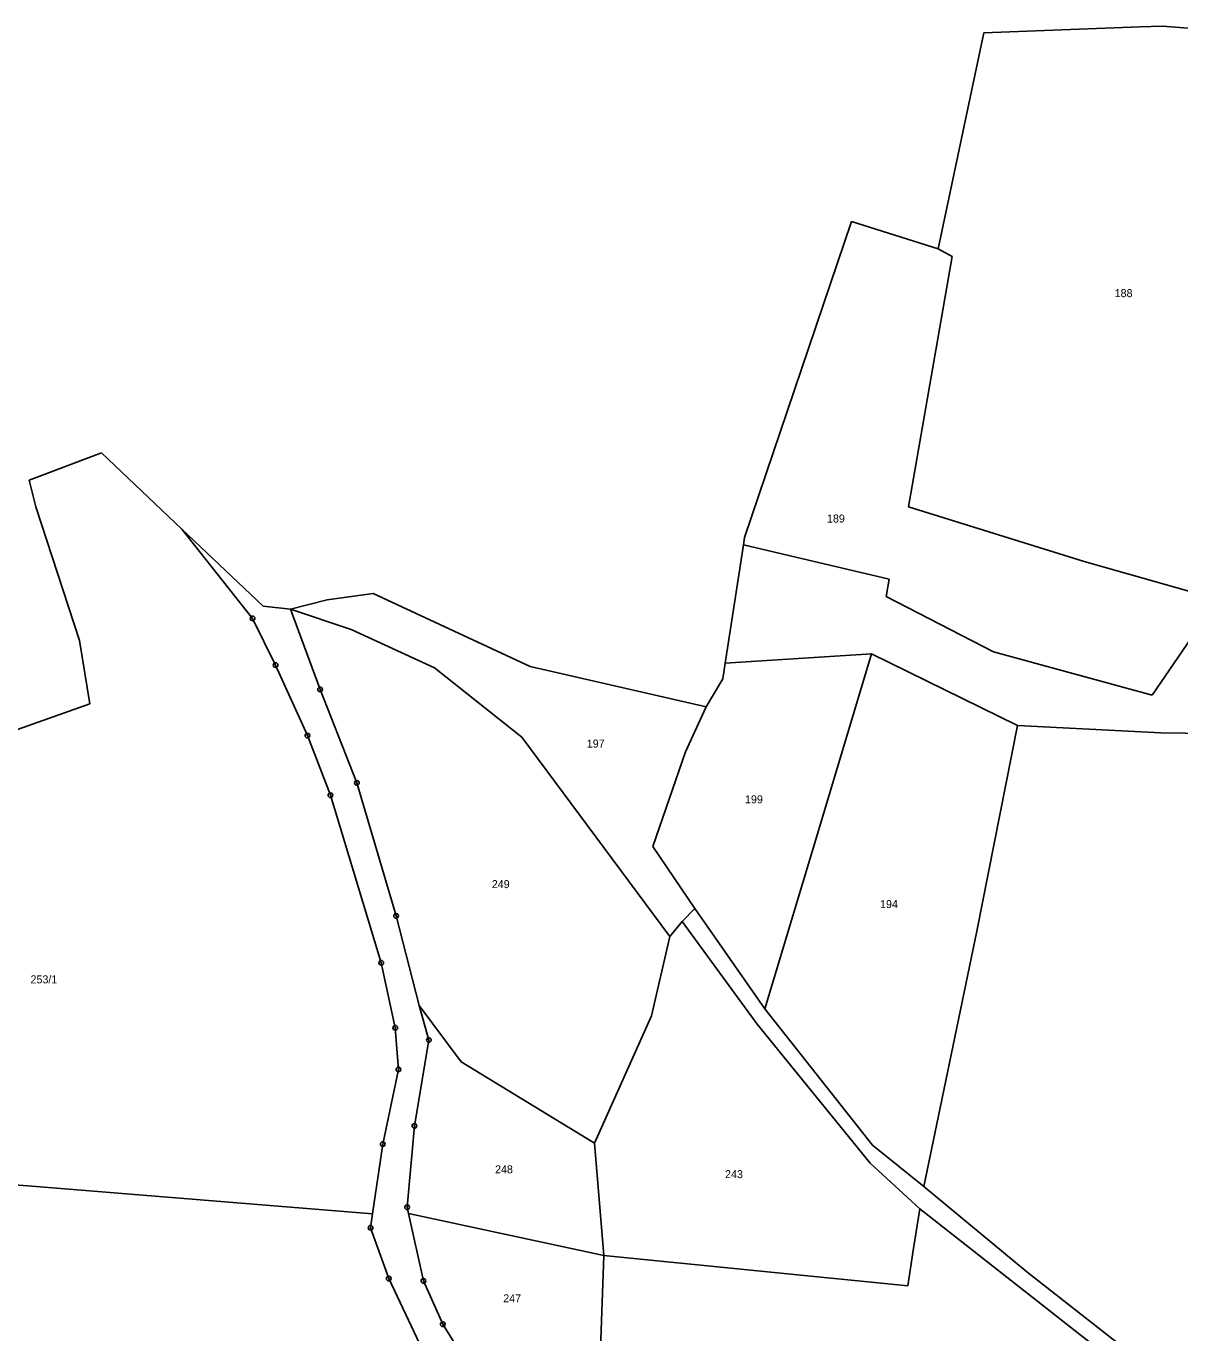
# Model space of a CAD drawing. Extents: x -791548 to -789311, y -1142631 to -1140855.
# Drawn here: x -790850.9 to -790605.8, y -1141528.8 to -1141251.3 of the extents above; entities that cross this region are included whole.
import ezdxf
from ezdxf.enums import TextEntityAlignment as Align

# ---------------------------------------------------------------- set-up
doc = ezdxf.new("R2010")
doc.units = 0
doc.header["$LTSCALE"] = 0.68
doc.layers.add('1', color=7, linetype='Continuous', lineweight=25)
doc.layers.add('8', color=7, linetype='Continuous', lineweight=25)
doc.layers.add('2', color=7, linetype='Continuous')

msp = doc.modelspace()

# ---------------------------------------------------------------- linework, layer by layer
at = {"layer": '1'}
for p, q in [((-790614.36, -1141251.45), (-790647.44, -1141252.67)), ((-790609.55, -1141251.27), (-790614.36, -1141251.45)), ((-790574.52, -1141254.07), (-790609.55, -1141251.27)), ((-790647.44, -1141252.67), (-790657.14, -1141298.57)), ((-790675.61, -1141292.79), (-790698.28, -1141359.89)), ((-790657.14, -1141298.57), (-790675.61, -1141292.79)), ((-790654.21, -1141300.21), (-790657.14, -1141298.57)), ((-790663.5, -1141353.35), (-790654.21, -1141300.21)), ((-790834.89, -1141341.93), (-790850.23, -1141347.68)), ((-790817.82, -1141358.13), (-790834.89, -1141341.93)), ((-790850.23, -1141347.68), (-790848.82, -1141353.4)), ((-790848.82, -1141353.4), (-790839.58, -1141381.74)), ((-790626.13, -1141364.99), (-790663.5, -1141353.35)), ((-790800.56, -1141374.5), (-790817.82, -1141358.13)), ((-790817.82, -1141358.13), (-790802.79, -1141377.08)), ((-790702.42, -1141386.57), (-790698.52, -1141361.44)), ((-790698.52, -1141361.44), (-790698.28, -1141359.89)), ((-790698.52, -1141361.44), (-790667.55, -1141368.7)), ((-790601.94, -1141371.83), (-790626.13, -1141364.99)), ((-790667.55, -1141368.7), (-790668.23, -1141372.38)), ((-790786.92, -1141373.1), (-790794.77, -1141375.11)), ((-790777.15, -1141371.81), (-790786.92, -1141373.1)), ((-790743.82, -1141387.29), (-790777.15, -1141371.81)), ((-790668.23, -1141372.38), (-790645.38, -1141384.2)), ((-790794.77, -1141375.11), (-790800.56, -1141374.5)), ((-790788.45, -1141392.15), (-790794.77, -1141375.11)), ((-790794.77, -1141375.11), (-790781.85, -1141379.43)), ((-790802.79, -1141377.08), (-790797.92, -1141386.98)), ((-790839.58, -1141381.74), (-790837.35, -1141395.22)), ((-790781.85, -1141379.43), (-790764.16, -1141387.55)), ((-790611.73, -1141393.4), (-790603.44, -1141381.28)), ((-790702.42, -1141386.57), (-790671.34, -1141384.61)), ((-790681.9, -1141419.8), (-790671.34, -1141384.61)), ((-790671.34, -1141384.61), (-790640.29, -1141399.79)), ((-790645.38, -1141384.2), (-790611.73, -1141393.4)), ((-790797.92, -1141386.98), (-790791.15, -1141401.95)), ((-790706.45, -1141395.88), (-790743.82, -1141387.29)), ((-790702.94, -1141389.91), (-790702.42, -1141386.57)), ((-790764.16, -1141387.55), (-790745.6, -1141402.32)), ((-790702.94, -1141389.91), (-790706.45, -1141395.88)), ((-790780.64, -1141412), (-790788.45, -1141392.15)), ((-790837.35, -1141395.22), (-790890.23, -1141413.86)), ((-790710.85, -1141405.42), (-790706.45, -1141395.88)), ((-790648.97, -1141443.49), (-790640.29, -1141399.79)), ((-790640.29, -1141399.79), (-790609.89, -1141401.37)), ((-790609.89, -1141401.37), (-790575.13, -1141401.94)), ((-790791.15, -1141401.95), (-790786.26, -1141414.61)), ((-790745.6, -1141402.32), (-790714.19, -1141444.6)), ((-790717.81, -1141425.51), (-790710.85, -1141405.42)), ((-790772.31, -1141440.24), (-790780.64, -1141412)), ((-790786.26, -1141414.61), (-790775.45, -1141450.21)), ((-790693.99, -1141460.01), (-790681.9, -1141419.8)), ((-790708.84, -1141438.68), (-790717.81, -1141425.51)), ((-790767.42, -1141459.28), (-790772.31, -1141440.24)), ((-790711.57, -1141441.46), (-790708.84, -1141438.68)), ((-790693.99, -1141460.01), (-790708.84, -1141438.68)), ((-790714.19, -1141444.6), (-790711.57, -1141441.46)), ((-790711.57, -1141441.46), (-790695.63, -1141463.24)), ((-790718.06, -1141461.5), (-790714.19, -1141444.6)), ((-790660.22, -1141497.72), (-790648.97, -1141443.49)), ((-790775.45, -1141450.21), (-790772.49, -1141464.01)), ((-790767.42, -1141459.28), (-790758.52, -1141471.23)), ((-790765.33, -1141466.61), (-790767.42, -1141459.28)), ((-790718.06, -1141461.5), (-790730.19, -1141488.49)), ((-790671.09, -1141488.96), (-790693.99, -1141460.01)), ((-790772.49, -1141464.01), (-790771.82, -1141472.87)), ((-790695.63, -1141463.24), (-790671.61, -1141492.76)), ((-790768.42, -1141484.86), (-790765.33, -1141466.61)), ((-790771.82, -1141472.87), (-790775.13, -1141488.71)), ((-790758.52, -1141471.23), (-790730.19, -1141488.49)), ((-790769.97, -1141502.13), (-790768.42, -1141484.86)), ((-790775.13, -1141488.71), (-790777.29, -1141503.55)), ((-790660.22, -1141497.72), (-790671.09, -1141488.96)), ((-790938.64, -1141490.83), (-790848.75, -1141497.75)), ((-790671.61, -1141492.76), (-790661.03, -1141502.45)), ((-790848.75, -1141497.75), (-790777.29, -1141503.55)), ((-790638.34, -1141515.86), (-790660.22, -1141497.72)), ((-790777.29, -1141503.55), (-790777.72, -1141506.47)), ((-790769.7, -1141503.43), (-790769.97, -1141502.13)), ((-790766.49, -1141517.78), (-790769.7, -1141503.43)), ((-790661.03, -1141502.45), (-790662.47, -1141511.33)), ((-790616.11, -1141537.74), (-790661.03, -1141502.45)), ((-790777.72, -1141506.47), (-790773.86, -1141517.27)), ((-790728.86, -1141532.28), (-790728.17, -1141512.41)), ((-790663.58, -1141518.83), (-790728.17, -1141512.41)), ((-790662.47, -1141511.33), (-790663.58, -1141518.83)), ((-790773.86, -1141517.27), (-790765.51, -1141534.95)), ((-790762.39, -1141526.97), (-790766.49, -1141517.78)), ((-790607.61, -1141539.86), (-790638.34, -1141515.86)), ((-790758.27, -1141533.6), (-790762.39, -1141526.97))]:
    msp.add_line(p, q, dxfattribs=at)
msp.add_lwpolyline([(-790730.19, -1141488.49), (-790728.17, -1141512.41), (-790769.7, -1141503.43)], dxfattribs=at)
at = {"layer": '8'}
for centre, radius in [((-790802.7899, -1141377.08), 0.5), ((-790802.7899, -1141377.08), 0.0303), ((-790797.9199, -1141386.98), 0.5), ((-790797.9199, -1141386.98), 0.0303), ((-790788.4499, -1141392.15), 0.5), ((-790788.4499, -1141392.15), 0.0303), ((-790791.1499, -1141401.95), 0.5), ((-790791.1499, -1141401.95), 0.0303), ((-790780.6399, -1141412), 0.5), ((-790780.6399, -1141412), 0.0303), ((-790786.2599, -1141414.61), 0.5), ((-790786.2599, -1141414.61), 0.0303), ((-790772.3099, -1141440.24), 0.5), ((-790772.3099, -1141440.24), 0.0303), ((-790775.4499, -1141450.21), 0.5), ((-790775.4499, -1141450.21), 0.0303), ((-790772.4899, -1141464.01), 0.5), ((-790772.4899, -1141464.01), 0.0303), ((-790765.3299, -1141466.61), 0.5), ((-790765.3299, -1141466.61), 0.0303), ((-790771.8199, -1141472.87), 0.5), ((-790771.8199, -1141472.87), 0.0303), ((-790768.4199, -1141484.86), 0.5), ((-790768.4199, -1141484.86), 0.0303), ((-790775.1299, -1141488.71), 0.5), ((-790775.1299, -1141488.71), 0.0303), ((-790769.9699, -1141502.13), 0.5), ((-790769.9699, -1141502.13), 0.0303), ((-790777.7199, -1141506.47), 0.5), ((-790777.7199, -1141506.47), 0.0303), ((-790773.8599, -1141517.27), 0.5), ((-790773.8599, -1141517.27), 0.0303), ((-790766.4899, -1141517.78), 0.5), ((-790766.4899, -1141517.78), 0.0303), ((-790762.3899, -1141526.97), 0.5), ((-790762.3899, -1141526.97), 0.0303)]:
    msp.add_circle(centre, radius, dxfattribs=at)

# ---------------------------------------------------------------- texts
at = {"layer": '2'}
for s, p in [('188', (-790617.779, -1141308.832)), ('189', (-790678.889, -1141356.702)), ('197', (-790729.909, -1141404.502)), ('199', (-790696.299, -1141416.342)), ('249', (-790750.079, -1141434.352)), ('194', (-790667.619, -1141438.592)), ('253/1', (-790847.12, -1141454.582)), ('248', (-790749.399, -1141494.932)), ('243', (-790700.539, -1141495.952)), ('247', (-790747.659, -1141522.332))]:
    msp.add_text(s, height=1.7, dxfattribs=at).set_placement(p, align=Align.CENTER)

doc.saveas('drawing.dxf')
